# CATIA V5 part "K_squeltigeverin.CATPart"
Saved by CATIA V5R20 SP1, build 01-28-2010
Part number: squeltigeverin
Publications: "diamverin", "longtigeverin"
Bounding box of the stored display mesh (mm): x 0 to 160, y -10 to 10, z -10 to 10
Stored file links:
  G:\Khaled_CFAO_2011\SIL\SIL_GR2\zthiebault\Khaled\CAD_ThinkMOTION\K_squeltigeverin.CATPart
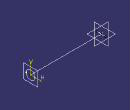
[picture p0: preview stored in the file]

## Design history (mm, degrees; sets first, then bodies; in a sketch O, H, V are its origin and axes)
Parameters
  diamverin = 20 mm
  longtigeverin = 160 mm
Set1
  Point1: (0, 0, 0)
  Line1: type Normal, RefPoint Point1, RefSkin yz-plane, Start 0, End 160 {= longtigeverin}
  Line2: type Normal, RefPoint Point1, RefSkin zx-plane, Start -10, End 10
  Plane1: type OffsetPt, RefPlane yz-plane, RefPoint vertex of Line1
  Sketch1 on Plane1, origin (160, 0, 0), H (0, 1, 0), V (0, 0, 1)
    circle A1 centre (0, 0) radius 10
    point P1 (0, 0)
    radius A1 = 10 {= diamverin /2}
    coincidence: P1 O
Body1 (main body)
